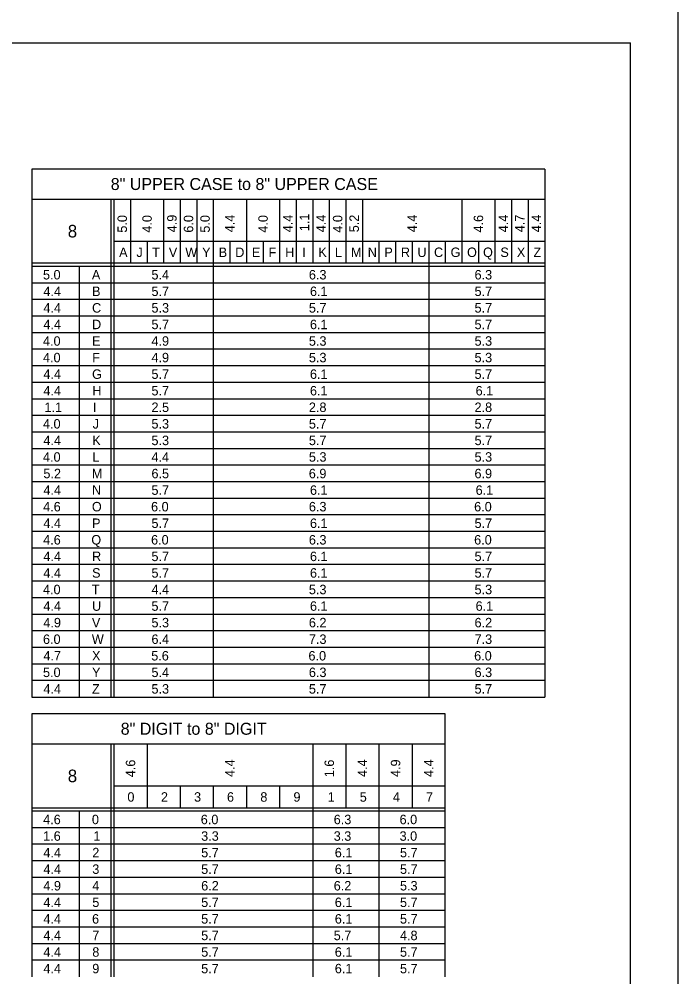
# Model space of a CAD drawing. Extents: x 638421 to 641849, y 297270 to 299646.
# Drawn here: x 640735.6 to 640944.3, y 297552.6 to 297856.1 of the extents above; entities that cross this region are included whole.
import ezdxf

# ---------------------------------------------------------------- set-up
doc = ezdxf.new("R2010")
doc.units = 0
for name, color, linetype in [('1', 7, 'Continuous'), ('2', 7, 'Continuous'), ('XCS-GRID-HVGL', 7, 'Continuous')]:
    doc.layers.add(name, color=color, linetype=linetype)

msp = doc.modelspace()

# ---------------------------------------------------------------- linework, layer by layer
at = {"layer": '1'}
for p in [(640143.31, 297848.63), (640929.31, 297284.63)]:
    msp.add_line(p, (640929.31, 297848.63), dxfattribs=at)
at = {"layer": '2'}
for p, q in [((640902.11, 297808.63), (640739.61, 297808.63)), ((640739.61, 297808.63), (640739.61, 297641.25)), ((640902.11, 297808.63), (640902.11, 297641.25)), ((640739.61, 297799.13), (640902.11, 297799.13)), ((640764.61, 297799.13), (640764.61, 297641.25)), ((640765.61, 297799.13), (640765.61, 297641.25)), ((640770.86, 297799.13), (640770.86, 297778.75)), ((640781.36, 297799.13), (640781.36, 297778.75)), ((640786.61, 297799.13), (640786.61, 297778.75)), ((640791.86, 297799.13), (640791.86, 297778.75)), ((640797.11, 297799.13), (640797.11, 297641.25)), ((640807.61, 297799.13), (640807.61, 297778.75)), ((640818.11, 297799.13), (640818.11, 297778.75)), ((640823.36, 297799.13), (640823.36, 297778.75)), ((640828.61, 297799.13), (640828.61, 297778.75)), ((640833.86, 297799.13), (640833.86, 297778.75)), ((640839.11, 297799.13), (640839.11, 297778.75)), ((640844.36, 297799.13), (640844.36, 297778.75)), ((640875.86, 297799.13), (640875.86, 297778.75)), ((640886.36, 297799.13), (640886.36, 297778.75)), ((640891.61, 297799.13), (640891.61, 297778.75)), ((640896.86, 297799.13), (640896.86, 297778.75)), ((640765.61, 297785.75), (640902.11, 297785.75)), ((640776.11, 297785.75), (640776.11, 297778.75)), ((640802.36, 297785.75), (640802.36, 297778.75)), ((640812.86, 297785.75), (640812.86, 297778.75)), ((640849.61, 297785.75), (640849.61, 297778.75)), ((640854.86, 297785.75), (640854.86, 297778.75)), ((640860.11, 297785.75), (640860.11, 297778.75)), ((640860.11, 297785.75), (640860.11, 297778.75)), ((640865.36, 297785.75), (640865.36, 297641.25)), ((640870.61, 297785.75), (640870.61, 297778.75)), ((640881.11, 297785.75), (640881.11, 297778.75)), ((640902.11, 297778.75), (640739.61, 297778.75)), ((640902.11, 297777.75), (640739.61, 297777.75)), ((640754.61, 297777.75), (640754.61, 297641.25)), ((640902.11, 297772.5), (640739.61, 297772.5)), ((640902.11, 297767.25), (640739.61, 297767.25)), ((640902.11, 297762), (640739.61, 297762)), ((640902.11, 297756.75), (640739.61, 297756.75)), ((640902.11, 297751.5), (640739.61, 297751.5)), ((640902.11, 297746.25), (640739.61, 297746.25)), ((640902.11, 297741), (640739.61, 297741)), ((640902.11, 297735.75), (640739.61, 297735.75)), ((640902.11, 297730.5), (640739.61, 297730.5)), ((640902.11, 297725.25), (640739.61, 297725.25)), ((640902.11, 297720), (640739.61, 297720)), ((640902.11, 297714.75), (640739.61, 297714.75)), ((640902.11, 297709.5), (640739.61, 297709.5)), ((640902.11, 297704.25), (640739.61, 297704.25)), ((640902.11, 297699), (640739.61, 297699)), ((640902.11, 297693.75), (640739.61, 297693.75)), ((640902.11, 297688.5), (640739.61, 297688.5)), ((640902.11, 297683.25), (640739.61, 297683.25)), ((640902.11, 297678), (640739.61, 297678)), ((640902.11, 297672.75), (640739.61, 297672.75)), ((640902.11, 297667.5), (640739.61, 297667.5)), ((640902.11, 297662.25), (640739.61, 297662.25)), ((640902.11, 297657), (640739.61, 297657)), ((640902.11, 297651.75), (640739.61, 297651.75)), ((640902.11, 297646.5), (640739.61, 297646.5)), ((640739.61, 297641.25), (640739.61, 297641.25)), ((640739.61, 297641.25), (640902.11, 297641.25)), ((640870.61, 297636), (640739.61, 297636)), ((640739.61, 297636), (640739.61, 297552.63)), ((640870.61, 297552.63), (640870.61, 297636)), ((640739.61, 297626.5), (640870.61, 297626.5)), ((640764.61, 297626.5), (640764.61, 297552.63)), ((640765.61, 297626.5), (640765.61, 297552.63)), ((640776.11, 297626.5), (640776.11, 297606.13)), ((640828.61, 297626.5), (640828.61, 297552.63)), ((640839.11, 297626.5), (640839.11, 297606.13)), ((640849.61, 297626.5), (640849.61, 297552.63)), ((640860.11, 297626.5), (640860.11, 297606.13)), ((640765.61, 297613.13), (640870.61, 297613.13)), ((640786.61, 297613.13), (640786.61, 297606.13)), ((640797.11, 297613.13), (640797.11, 297606.13)), ((640807.61, 297613.13), (640807.61, 297606.13)), ((640818.11, 297613.13), (640818.11, 297606.13)), ((640870.61, 297606.13), (640739.61, 297606.13)), ((640870.61, 297605.13), (640739.61, 297605.13)), ((640754.61, 297605.13), (640754.61, 297552.63)), ((640870.61, 297599.88), (640739.61, 297599.88)), ((640870.61, 297594.63), (640739.61, 297594.63)), ((640870.61, 297589.38), (640739.61, 297589.38)), ((640870.61, 297584.13), (640739.61, 297584.13)), ((640870.61, 297578.88), (640739.61, 297578.88)), ((640870.61, 297573.63), (640739.61, 297573.63)), ((640870.61, 297568.38), (640739.61, 297568.38)), ((640870.61, 297563.13), (640739.61, 297563.13)), ((640870.61, 297557.88), (640739.61, 297557.88))]:
    msp.add_line(p, q, dxfattribs=at)
at = {"layer": 'XCS-GRID-HVGL'}
msp.add_lwpolyline([(640103.31, 297863.63), (640944.31, 297863.63), (640944.31, 297269.63), (640103.31, 297269.63)], close=True, dxfattribs=at)

# ---------------------------------------------------------------- texts
at = {"layer": '2'}
for s, height, p in [('8" UPPER CASE to 8" UPPER CASE', 3.8, (640764.6, 297801.98)), ('8', 4, (640750.98, 297786.94)), ('A', 3, (640767.26, 297780.75)), ('J', 3, (640772.74, 297780.75)), ('T', 3, (640777.74, 297780.75)), ('V', 3, (640783.01, 297780.75)), ('W', 3, (640788.23, 297780.75)), ('Y', 3, (640793.54, 297780.75)), ('B', 3, (640798.8, 297780.75)), ('D', 3, (640804.05, 297780.75)), ('E', 3, (640809.32, 297780.75)), ('F', 3, (640814.62, 297780.75)), ('H', 3, (640819.89, 297780.75)), ('I', 3, (640825.3, 297780.75)), ('K', 3, (640830.39, 297780.75)), ('L', 3, (640835.64, 297780.75)), ('M', 3, (640840.73, 297780.75)), ('N', 3, (640846.05, 297780.75)), ('P', 3, (640851.3, 297780.75)), ('R', 3, (640856.55, 297780.75)), ('U', 3, (640861.79, 297780.75)), ('C', 3, (640867.05, 297780.75)), ('G', 3, (640872.3, 297780.75)), ('O', 3, (640877.51, 297780.75)), ('Q', 3, (640882.58, 297780.75)), ('S', 3, (640888.07, 297780.75)), ('X', 3, (640893.29, 297780.75)), ('Z', 3, (640898.55, 297780.75)), ('5.0', 3, (640743.13, 297773.63)), ('A', 3, (640758.63, 297773.63)), ('5.4', 3, (640777.51, 297773.63)), ('6.3', 3, (640827.39, 297773.63)), ('6.3', 3, (640879.89, 297773.63)), ('4.4', 3, (640743.26, 297768.38)), ('B', 3, (640758.68, 297768.38)), ('5.7', 3, (640777.51, 297768.38)), ('6.1', 3, (640827.73, 297768.38)), ('5.7', 3, (640879.89, 297768.38)), ('4.4', 3, (640743.26, 297763.13)), ('C', 3, (640758.68, 297763.13)), ('5.3', 3, (640777.51, 297763.13)), ('5.7', 3, (640827.39, 297763.13)), ('5.7', 3, (640879.89, 297763.13)), ('6.1', 3, (640827.73, 297757.88)), ('4.4', 3, (640743.26, 297757.88)), ('D', 3, (640758.68, 297757.88)), ('5.7', 3, (640777.51, 297757.88)), ('5.7', 3, (640879.89, 297757.88)), ('4.0', 3, (640743.13, 297752.63)), ('E', 3, (640758.69, 297752.63)), ('4.9', 3, (640777.5, 297752.63)), ('5.3', 3, (640827.39, 297752.63)), ('5.3', 3, (640879.89, 297752.63)), ('4.0', 3, (640743.13, 297747.38)), ('F', 3, (640758.75, 297747.38)), ('4.9', 3, (640777.5, 297747.38)), ('5.3', 3, (640827.39, 297747.38)), ('5.3', 3, (640879.89, 297747.38)), ('4.4', 3, (640743.26, 297742.13)), ('G', 3, (640758.68, 297742.13)), ('5.7', 3, (640777.51, 297742.13)), ('6.1', 3, (640827.73, 297742.13)), ('5.7', 3, (640879.89, 297742.13)), ('4.4', 3, (640743.26, 297736.88)), ('H', 3, (640758.76, 297736.88)), ('5.7', 3, (640777.51, 297736.88)), ('6.1', 3, (640827.73, 297736.88)), ('6.1', 3, (640880.23, 297736.88)), ('1.1', 3, (640743.6, 297731.63)), ('I', 3, (640758.93, 297731.63)), ('2.5', 3, (640777.51, 297731.63)), ('2.8', 3, (640827.39, 297731.63)), ('2.8', 3, (640879.89, 297731.63)), ('4.0', 3, (640743.13, 297726.38)), ('J', 3, (640758.87, 297726.38)), ('5.3', 3, (640777.51, 297726.38)), ('5.7', 3, (640827.39, 297726.38)), ('5.7', 3, (640879.89, 297726.38)), ('4.4', 3, (640743.26, 297721.13)), ('K', 3, (640758.76, 297721.13)), ('5.3', 3, (640777.51, 297721.13)), ('5.7', 3, (640827.39, 297721.13)), ('5.7', 3, (640879.89, 297721.13)), ('4.0', 3, (640743.13, 297715.88)), ('L', 3, (640758.76, 297715.88)), ('4.4', 3, (640777.51, 297715.88)), ('5.3', 3, (640827.39, 297715.88)), ('5.3', 3, (640879.89, 297715.88)), ('5.2', 3, (640743.26, 297710.63)), ('M', 3, (640758.61, 297710.63)), ('6.5', 3, (640777.51, 297710.63)), ('6.9', 3, (640827.37, 297710.63)), ('6.9', 3, (640879.87, 297710.63)), ('4.4', 3, (640743.26, 297705.38)), ('N', 3, (640758.68, 297705.38)), ('5.7', 3, (640777.51, 297705.38)), ('6.1', 3, (640827.73, 297705.38)), ('6.1', 3, (640880.23, 297705.38)), ('4.6', 3, (640743.18, 297700.13)), ('O', 3, (640758.63, 297700.13)), ('6.0', 3, (640777.38, 297700.13)), ('6.3', 3, (640827.39, 297700.13)), ('6.0', 3, (640879.76, 297700.13)), ('4.4', 3, (640743.26, 297694.88)), ('P', 3, (640758.68, 297694.88)), ('5.7', 3, (640777.51, 297694.88)), ('6.1', 3, (640827.73, 297694.88)), ('5.7', 3, (640879.89, 297694.88)), ('4.6', 3, (640743.18, 297689.63)), ('Q', 3, (640758.45, 297689.63)), ('6.0', 3, (640777.38, 297689.63)), ('6.3', 3, (640827.39, 297689.63)), ('6.0', 3, (640879.76, 297689.63)), ('4.4', 3, (640743.26, 297684.38)), ('R', 3, (640758.68, 297684.38)), ('5.7', 3, (640777.51, 297684.38)), ('6.1', 3, (640827.73, 297684.38)), ('5.7', 3, (640879.89, 297684.38)), ('4.4', 3, (640743.26, 297679.13)), ('S', 3, (640758.69, 297679.13)), ('5.7', 3, (640777.51, 297679.13)), ('6.1', 3, (640827.73, 297679.13)), ('5.7', 3, (640879.89, 297679.13)), ('4.0', 3, (640743.13, 297673.88)), ('T', 3, (640758.62, 297673.88)), ('4.4', 3, (640777.51, 297673.88)), ('5.3', 3, (640827.39, 297673.88)), ('5.3', 3, (640879.89, 297673.88)), ('4.4', 3, (640743.26, 297668.63)), ('U', 3, (640758.67, 297668.63)), ('5.7', 3, (640777.51, 297668.63)), ('6.1', 3, (640827.73, 297668.63)), ('6.1', 3, (640880.23, 297668.63)), ('4.9', 3, (640743.25, 297663.38)), ('V', 3, (640758.63, 297663.38)), ('5.3', 3, (640777.51, 297663.38)), ('6.2', 3, (640827.39, 297663.38)), ('6.2', 3, (640879.89, 297663.38)), ('6.0', 3, (640743.13, 297658.13)), ('W', 3, (640758.61, 297658.13)), ('6.4', 3, (640777.51, 297658.13)), ('7.3', 3, (640827.39, 297658.13)), ('7.3', 3, (640879.89, 297658.13)), ('4.7', 3, (640743.26, 297652.88)), ('X', 3, (640758.67, 297652.88)), ('5.6', 3, (640777.43, 297652.88)), ('6.0', 3, (640827.26, 297652.88)), ('6.0', 3, (640879.76, 297652.88)), ('5.0', 3, (640743.13, 297647.63)), ('Y', 3, (640758.67, 297647.63)), ('5.4', 3, (640777.51, 297647.63)), ('6.3', 3, (640827.39, 297647.63)), ('6.3', 3, (640879.89, 297647.63)), ('4.4', 3, (640743.26, 297642.38)), ('Z', 3, (640758.68, 297642.38)), ('5.3', 3, (640777.51, 297642.38)), ('5.7', 3, (640827.39, 297642.38)), ('5.7', 3, (640879.89, 297642.38)), ('8" DIGIT to 8" DIGIT', 3.8, (640767.76, 297629.35)), ('8', 4, (640750.98, 297614.31)), ('0', 3, (640769.88, 297608.13)), ('2', 3, (640780.51, 297608.13)), ('3', 3, (640791.01, 297608.13)), ('6', 3, (640801.43, 297608.13)), ('8', 3, (640812.01, 297608.13)), ('9', 3, (640822.5, 297608.13)), ('1', 3, (640833.35, 297608.13)), ('5', 3, (640843.51, 297608.13)), ('4', 3, (640854.01, 297608.13)), ('7', 3, (640864.51, 297608.13)), ('4.6', 3, (640743.18, 297601)), ('0', 3, (640758.63, 297601)), ('6.0', 3, (640793.13, 297601)), ('6.3', 3, (640835.26, 297601)), ('6.0', 3, (640856.13, 297601)), ('1.6', 3, (640743.18, 297595.75)), ('1', 3, (640759.1, 297595.75)), ('3.3', 3, (640793.26, 297595.75)), ('3.3', 3, (640835.26, 297595.75)), ('3.0', 3, (640856.13, 297595.75)), ('4.4', 3, (640743.26, 297590.5)), ('2', 3, (640758.76, 297590.5)), ('5.7', 3, (640793.26, 297590.5)), ('6.1', 3, (640835.6, 297590.5)), ('5.7', 3, (640856.26, 297590.5)), ('4.4', 3, (640743.26, 297585.25)), ('3', 3, (640758.76, 297585.25)), ('5.7', 3, (640793.26, 297585.25)), ('6.1', 3, (640835.6, 297585.25)), ('5.7', 3, (640856.26, 297585.25)), ('4.9', 3, (640743.25, 297580)), ('4', 3, (640758.76, 297580)), ('6.2', 3, (640793.26, 297580)), ('6.2', 3, (640835.26, 297580)), ('5.3', 3, (640856.26, 297580)), ('4.4', 3, (640743.26, 297574.75)), ('5', 3, (640758.76, 297574.75)), ('5.7', 3, (640793.26, 297574.75)), ('6.1', 3, (640835.6, 297574.75)), ('5.7', 3, (640856.26, 297574.75)), ('4.4', 3, (640743.26, 297569.5)), ('6', 3, (640758.68, 297569.5)), ('5.7', 3, (640793.26, 297569.5)), ('6.1', 3, (640835.6, 297569.5)), ('5.7', 3, (640856.26, 297569.5)), ('4.4', 3, (640743.26, 297564.25)), ('7', 3, (640758.76, 297564.25)), ('5.7', 3, (640793.26, 297564.25)), ('5.7', 3, (640835.26, 297564.25)), ('4.8', 3, (640856.26, 297564.25)), ('4.4', 3, (640743.26, 297559)), ('8', 3, (640758.76, 297559)), ('5.7', 3, (640793.26, 297559)), ('6.1', 3, (640835.6, 297559)), ('5.7', 3, (640856.26, 297559)), ('4.4', 3, (640743.26, 297553.75)), ('9', 3, (640758.75, 297553.75)), ('5.7', 3, (640793.26, 297553.75)), ('6.1', 3, (640835.6, 297553.75)), ('5.7', 3, (640856.26, 297553.75))]:
    msp.add_text(s, height=height, dxfattribs=at).set_placement(p)
for s, p in [('1.1', (640827.49, 297788.93)), ('5.0', (640769.74, 297788.46)), ('4.0', (640777.61, 297788.46)), ('4.9', (640785.49, 297788.58)), ('6.0', (640790.74, 297788.46)), ('5.0', (640795.99, 297788.46)), ('4.4', (640803.86, 297788.59)), ('4.0', (640814.36, 297788.46)), ('4.4', (640822.24, 297788.59)), ('4.4', (640832.74, 297788.59)), ('4.0', (640837.99, 297788.46)), ('5.2', (640843.24, 297788.59)), ('4.4', (640861.61, 297788.59)), ('4.6', (640882.61, 297788.51)), ('4.4', (640890.49, 297788.59)), ('4.7', (640895.74, 297788.59)), ('4.4', (640900.99, 297788.59)), ('4.6', (640772.36, 297615.88)), ('4.4', (640803.86, 297615.96)), ('1.6', (640835.36, 297615.88)), ('4.4', (640845.86, 297615.96)), ('4.9', (640856.36, 297615.95)), ('4.4', (640866.86, 297615.96))]:
    msp.add_text(s, height=3, rotation=90, dxfattribs=at).set_placement(p)

doc.saveas('drawing.dxf')
